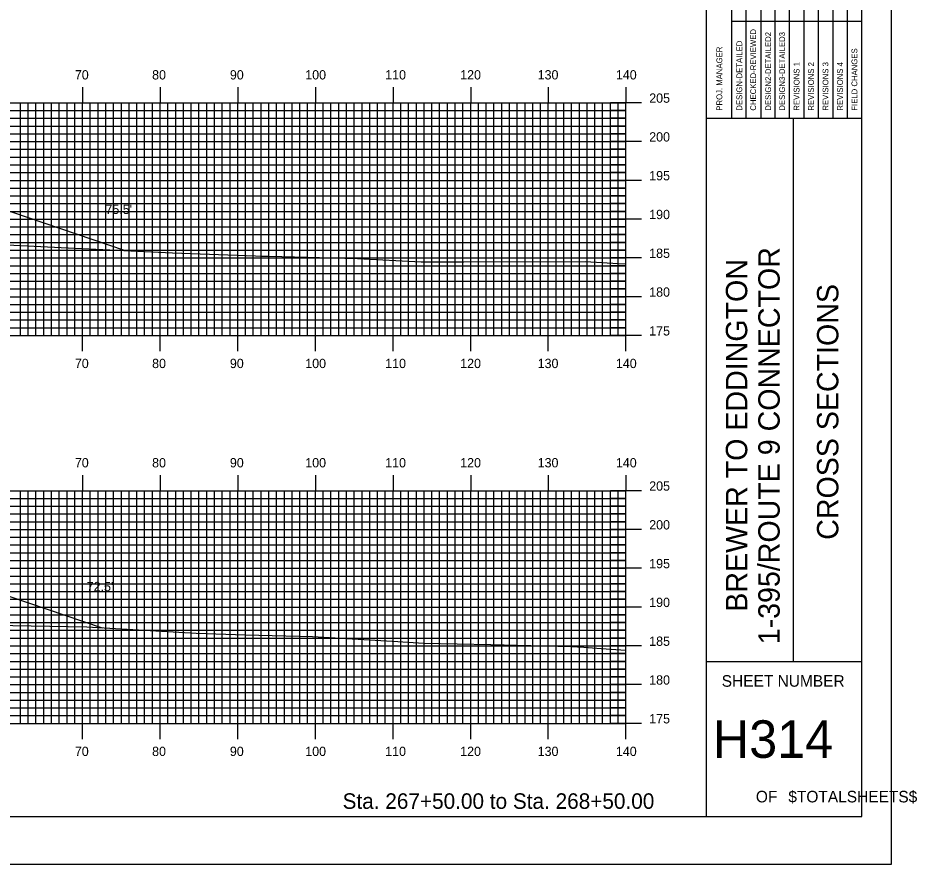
# Model space of a CAD drawing. Extents: x 1807832 to 1808175, y 442591 to 442811.
# Drawn here: x 1808059.5 to 1808175.3, y 442590.5 to 442699.6 of the extents above; entities that cross this region are included whole.
import ezdxf

# ---------------------------------------------------------------- set-up
doc = ezdxf.new("R2010")
doc.units = 0
for name, color, linetype in [('BORDER', 7, 'Continuous'), ('D_Roadway_SlopeLines', 7, 'Continuous'), ('D_Text_Standard', 7, 'Continuous'), ('H_V ANNOTATION', 7, 'Continuous'), ('MAJOR', 7, 'Continuous'), ('MINOR', 7, 'Continuous'), ('PLOT BOUNDARY', 7, 'Continuous'), ('S_Roadway_Centerline', 7, 'Continuous')]:
    doc.layers.add(name, color=color, linetype=linetype)

msp = doc.modelspace()

# ---------------------------------------------------------------- linework, layer by layer
at = {"layer": 'BORDER'}
for p, q in [((1808148.18, 442596.67), (1808148.18, 442806.67)), ((1808148.18, 442686.67), (1808168.18, 442686.67)), ((1808159.37, 442616.67), (1808159.37, 442686.67)), ((1808148.18, 442616.67), (1808168.18, 442616.67))]:
    msp.add_line(p, q, dxfattribs=at)
msp.add_lwpolyline([(1807848.18, 442596.67), (1808168.18, 442596.67), (1808168.18, 442806.67), (1807848.18, 442806.67)], close=True, dxfattribs=at)
for points in [[(1808153.28, 442686.68), (1808153.28, 442721.67)], [(1808155.14, 442721.67), (1808155.14, 442686.68)], [(1808157.01, 442686.68), (1808157.01, 442721.67)], [(1808158.87, 442686.68), (1808158.87, 442721.67)], [(1808160.73, 442686.68), (1808160.73, 442721.67)], [(1808162.6, 442686.68), (1808162.6, 442721.67)], [(1808164.46, 442686.68), (1808164.46, 442721.67)], [(1808166.32, 442686.68), (1808166.32, 442721.67)], [(1808151.42, 442686.68), (1808151.42, 442720.26)], [(1808151.41, 442699.17), (1808168.18, 442699.17)]]:
    msp.add_lwpolyline(points, dxfattribs=at)
at = {"layer": 'D_Roadway_SlopeLines'}
for points in [[(1808051.29, 442677.07), (1808054.53, 442675.97), (1808073.28, 442669.62)], [(1808043.37, 442630.1), (1808046.6, 442629.01), (1808070.29, 442620.99)]]:
    msp.add_lwpolyline(points, dxfattribs=at)
at = {"layer": 'MAJOR'}
for p, q in [((1808067.78, 442690.67), (1808067.78, 442688.67)), ((1808077.78, 442690.67), (1808077.78, 442688.67)), ((1808087.78, 442690.67), (1808087.78, 442688.67)), ((1808097.78, 442690.67), (1808097.78, 442688.67)), ((1808107.78, 442690.67), (1808107.78, 442688.67)), ((1808117.78, 442690.67), (1808117.78, 442688.67)), ((1808127.78, 442690.67), (1808127.78, 442688.67)), ((1808137.78, 442690.67), (1808137.78, 442688.67)), ((1807857.78, 442688.67), (1808137.78, 442688.67)), ((1807857.78, 442688.67), (1808137.78, 442688.67)), ((1808067.78, 442658.67), (1808067.78, 442688.67)), ((1808077.78, 442658.67), (1808077.78, 442688.67)), ((1808087.78, 442658.67), (1808087.78, 442688.67)), ((1808097.78, 442658.67), (1808097.78, 442688.67)), ((1808107.78, 442658.67), (1808107.78, 442688.67)), ((1808117.78, 442658.67), (1808117.78, 442688.67)), ((1808127.78, 442658.67), (1808127.78, 442688.67)), ((1808139.79, 442688.67), (1808135.78, 442688.67)), ((1808137.78, 442658.67), (1808137.78, 442688.67)), ((1808137.78, 442658.67), (1808137.78, 442688.67)), ((1807857.78, 442683.67), (1808137.78, 442683.67)), ((1808139.79, 442683.67), (1808135.78, 442683.67)), ((1807857.78, 442678.67), (1808137.78, 442678.67)), ((1808139.79, 442678.67), (1808135.78, 442678.67)), ((1807857.78, 442673.67), (1808137.78, 442673.67)), ((1808139.79, 442673.67), (1808135.78, 442673.67)), ((1807857.78, 442668.67), (1808137.78, 442668.67)), ((1808139.79, 442668.67), (1808135.78, 442668.67)), ((1807857.78, 442663.67), (1808137.78, 442663.67)), ((1808139.79, 442663.67), (1808135.78, 442663.67)), ((1807857.78, 442658.67), (1808137.78, 442658.67)), ((1807857.78, 442658.67), (1808137.78, 442658.67)), ((1808067.78, 442656.66), (1808067.78, 442658.67)), ((1808077.78, 442656.66), (1808077.78, 442658.67)), ((1808087.78, 442656.66), (1808087.78, 442658.67)), ((1808097.78, 442656.66), (1808097.78, 442658.67)), ((1808107.78, 442656.66), (1808107.78, 442658.67)), ((1808117.78, 442656.66), (1808117.78, 442658.67)), ((1808127.78, 442656.66), (1808127.78, 442658.67)), ((1808139.79, 442658.67), (1808135.78, 442658.67)), ((1808137.78, 442656.66), (1808137.78, 442658.67)), ((1808067.78, 442640.67), (1808067.78, 442638.67)), ((1808077.78, 442640.67), (1808077.78, 442638.67)), ((1808087.78, 442640.67), (1808087.78, 442638.67)), ((1808097.78, 442640.67), (1808097.78, 442638.67)), ((1808107.78, 442640.67), (1808107.78, 442638.67)), ((1808117.78, 442640.67), (1808117.78, 442638.67)), ((1808127.78, 442640.67), (1808127.78, 442638.67)), ((1808137.78, 442640.67), (1808137.78, 442638.67)), ((1807857.78, 442638.67), (1808137.78, 442638.67)), ((1807857.78, 442638.67), (1808137.78, 442638.67)), ((1808067.78, 442608.67), (1808067.78, 442638.67)), ((1808077.78, 442608.67), (1808077.78, 442638.67)), ((1808087.78, 442608.67), (1808087.78, 442638.67)), ((1808097.78, 442608.67), (1808097.78, 442638.67)), ((1808107.78, 442608.67), (1808107.78, 442638.67)), ((1808117.78, 442608.67), (1808117.78, 442638.67)), ((1808127.78, 442608.67), (1808127.78, 442638.67)), ((1808139.79, 442638.67), (1808135.78, 442638.67)), ((1808137.78, 442608.67), (1808137.78, 442638.67)), ((1808137.78, 442608.67), (1808137.78, 442638.67)), ((1807857.78, 442633.67), (1808137.78, 442633.67)), ((1808139.79, 442633.67), (1808135.78, 442633.67)), ((1807857.78, 442628.67), (1808137.78, 442628.67)), ((1808139.79, 442628.67), (1808135.78, 442628.67)), ((1807857.78, 442623.67), (1808137.78, 442623.67)), ((1808139.79, 442623.67), (1808135.78, 442623.67)), ((1807857.78, 442618.67), (1808137.78, 442618.67)), ((1808139.79, 442618.67), (1808135.78, 442618.67)), ((1807857.78, 442613.67), (1808137.78, 442613.67)), ((1808139.79, 442613.67), (1808135.78, 442613.67)), ((1807857.78, 442608.67), (1808137.78, 442608.67)), ((1807857.78, 442608.67), (1808137.78, 442608.67)), ((1808067.78, 442606.66), (1808067.78, 442608.67)), ((1808077.78, 442606.66), (1808077.78, 442608.67)), ((1808087.78, 442606.66), (1808087.78, 442608.67)), ((1808097.78, 442606.66), (1808097.78, 442608.67)), ((1808107.78, 442606.66), (1808107.78, 442608.67)), ((1808117.78, 442606.66), (1808117.78, 442608.67)), ((1808127.78, 442606.66), (1808127.78, 442608.67)), ((1808139.79, 442608.67), (1808135.78, 442608.67)), ((1808137.78, 442606.66), (1808137.78, 442608.67))]:
    msp.add_line(p, q, dxfattribs=at)
at = {"layer": 'MINOR'}
for p, q in [((1808059.78, 442658.67), (1808059.78, 442688.67)), ((1808060.78, 442658.67), (1808060.78, 442688.67)), ((1808061.78, 442658.67), (1808061.78, 442688.67)), ((1808062.78, 442658.67), (1808062.78, 442688.67)), ((1808063.78, 442658.67), (1808063.78, 442688.67)), ((1808064.78, 442658.67), (1808064.78, 442688.67)), ((1808065.78, 442658.67), (1808065.78, 442688.67)), ((1808066.78, 442658.67), (1808066.78, 442688.67)), ((1808068.78, 442658.67), (1808068.78, 442688.67)), ((1808069.78, 442658.67), (1808069.78, 442688.67)), ((1808070.78, 442658.67), (1808070.78, 442688.67)), ((1808071.78, 442658.67), (1808071.78, 442688.67)), ((1808072.78, 442658.67), (1808072.78, 442688.67)), ((1808073.78, 442658.67), (1808073.78, 442688.67)), ((1808074.78, 442658.67), (1808074.78, 442688.67)), ((1808075.78, 442658.67), (1808075.78, 442688.67)), ((1808076.78, 442658.67), (1808076.78, 442688.67)), ((1808078.78, 442658.67), (1808078.78, 442688.67)), ((1808079.78, 442658.67), (1808079.78, 442688.67)), ((1808080.78, 442658.67), (1808080.78, 442688.67)), ((1808081.78, 442658.67), (1808081.78, 442688.67)), ((1808082.78, 442658.67), (1808082.78, 442688.67)), ((1808083.78, 442658.67), (1808083.78, 442688.67)), ((1808084.78, 442658.67), (1808084.78, 442688.67)), ((1808085.78, 442658.67), (1808085.78, 442688.67)), ((1808086.78, 442658.67), (1808086.78, 442688.67)), ((1808088.78, 442658.67), (1808088.78, 442688.67)), ((1808089.78, 442658.67), (1808089.78, 442688.67)), ((1808090.78, 442658.67), (1808090.78, 442688.67)), ((1808091.78, 442658.67), (1808091.78, 442688.67)), ((1808092.78, 442658.67), (1808092.78, 442688.67)), ((1808093.78, 442658.67), (1808093.78, 442688.67)), ((1808094.78, 442658.67), (1808094.78, 442688.67)), ((1808095.78, 442658.67), (1808095.78, 442688.67)), ((1808096.78, 442658.67), (1808096.78, 442688.67)), ((1808098.78, 442658.67), (1808098.78, 442688.67)), ((1808099.78, 442658.67), (1808099.78, 442688.67)), ((1808100.78, 442658.67), (1808100.78, 442688.67)), ((1808101.78, 442658.67), (1808101.78, 442688.67)), ((1808102.78, 442658.67), (1808102.78, 442688.67)), ((1808103.78, 442658.67), (1808103.78, 442688.67)), ((1808104.78, 442658.67), (1808104.78, 442688.67)), ((1808105.78, 442658.67), (1808105.78, 442688.67)), ((1808106.78, 442658.67), (1808106.78, 442688.67)), ((1808108.78, 442658.67), (1808108.78, 442688.67)), ((1808109.78, 442658.67), (1808109.78, 442688.67)), ((1808110.78, 442658.67), (1808110.78, 442688.67)), ((1808111.78, 442658.67), (1808111.78, 442688.67)), ((1808112.78, 442658.67), (1808112.78, 442688.67)), ((1808113.78, 442658.67), (1808113.78, 442688.67)), ((1808114.78, 442658.67), (1808114.78, 442688.67)), ((1808115.78, 442658.67), (1808115.78, 442688.67)), ((1808116.78, 442658.67), (1808116.78, 442688.67)), ((1808118.78, 442658.67), (1808118.78, 442688.67)), ((1808119.78, 442658.67), (1808119.78, 442688.67)), ((1808120.78, 442658.67), (1808120.78, 442688.67)), ((1808121.78, 442658.67), (1808121.78, 442688.67)), ((1808122.78, 442658.67), (1808122.78, 442688.67)), ((1808123.78, 442658.67), (1808123.78, 442688.67)), ((1808124.78, 442658.67), (1808124.78, 442688.67)), ((1808125.78, 442658.67), (1808125.78, 442688.67)), ((1808126.78, 442658.67), (1808126.78, 442688.67)), ((1808128.78, 442658.67), (1808128.78, 442688.67)), ((1808129.78, 442658.67), (1808129.78, 442688.67)), ((1808130.78, 442658.67), (1808130.78, 442688.67)), ((1808131.78, 442658.67), (1808131.78, 442688.67)), ((1808132.78, 442658.67), (1808132.78, 442688.67)), ((1808133.78, 442658.67), (1808133.78, 442688.67)), ((1808134.78, 442658.67), (1808134.78, 442688.67)), ((1808135.78, 442658.67), (1808135.78, 442688.67)), ((1808136.78, 442658.67), (1808136.78, 442688.67)), ((1807857.78, 442687.67), (1808137.78, 442687.67)), ((1808137.78, 442687.67), (1808135.78, 442687.67)), ((1807857.78, 442686.67), (1808137.78, 442686.67)), ((1808137.78, 442686.67), (1808135.78, 442686.67)), ((1807857.78, 442685.67), (1808137.78, 442685.67)), ((1808137.78, 442685.67), (1808135.78, 442685.67)), ((1807857.78, 442684.67), (1808137.78, 442684.67)), ((1808137.78, 442684.67), (1808135.78, 442684.67)), ((1807857.78, 442682.67), (1808137.78, 442682.67)), ((1808137.78, 442682.67), (1808135.78, 442682.67)), ((1807857.78, 442681.67), (1808137.78, 442681.67)), ((1808137.78, 442681.67), (1808135.78, 442681.67)), ((1807857.78, 442680.67), (1808137.78, 442680.67)), ((1808137.78, 442680.67), (1808135.78, 442680.67)), ((1807857.78, 442679.67), (1808137.78, 442679.67)), ((1808137.78, 442679.67), (1808135.78, 442679.67)), ((1807857.78, 442677.67), (1808137.78, 442677.67)), ((1808137.78, 442677.67), (1808135.78, 442677.67)), ((1807857.78, 442676.67), (1808137.78, 442676.67)), ((1808137.78, 442676.67), (1808135.78, 442676.67)), ((1807857.78, 442675.67), (1808137.78, 442675.67)), ((1807857.78, 442674.67), (1808137.78, 442674.67)), ((1808137.78, 442675.67), (1808135.78, 442675.67)), ((1808137.78, 442674.67), (1808135.78, 442674.67)), ((1807857.78, 442672.67), (1808137.78, 442672.67)), ((1808137.78, 442672.67), (1808135.78, 442672.67)), ((1807857.78, 442671.67), (1808137.78, 442671.67)), ((1808137.78, 442671.67), (1808135.78, 442671.67)), ((1807857.78, 442670.67), (1808137.78, 442670.67)), ((1808137.78, 442670.67), (1808135.78, 442670.67)), ((1807857.78, 442669.67), (1808137.78, 442669.67)), ((1808137.78, 442669.67), (1808135.78, 442669.67)), ((1807857.78, 442667.67), (1808137.78, 442667.67)), ((1808137.78, 442667.67), (1808135.78, 442667.67)), ((1807857.78, 442666.67), (1808137.78, 442666.67)), ((1808137.78, 442666.67), (1808135.78, 442666.67)), ((1807857.78, 442665.67), (1808137.78, 442665.67)), ((1808137.78, 442665.67), (1808135.78, 442665.67)), ((1807857.78, 442664.67), (1808137.78, 442664.67)), ((1808137.78, 442664.67), (1808135.78, 442664.67)), ((1807857.78, 442662.67), (1808137.78, 442662.67)), ((1808137.78, 442662.67), (1808135.78, 442662.67)), ((1807857.78, 442661.67), (1808137.78, 442661.67)), ((1807857.78, 442660.67), (1808137.78, 442660.67)), ((1808137.78, 442661.67), (1808135.78, 442661.67)), ((1808137.78, 442660.67), (1808135.78, 442660.67)), ((1807857.78, 442659.67), (1808137.78, 442659.67)), ((1808137.78, 442659.67), (1808135.78, 442659.67)), ((1808059.78, 442608.67), (1808059.78, 442638.67)), ((1808060.78, 442608.67), (1808060.78, 442638.67)), ((1808061.78, 442608.67), (1808061.78, 442638.67)), ((1808062.78, 442608.67), (1808062.78, 442638.67)), ((1808063.78, 442608.67), (1808063.78, 442638.67)), ((1808064.78, 442608.67), (1808064.78, 442638.67)), ((1808065.78, 442608.67), (1808065.78, 442638.67)), ((1808066.78, 442608.67), (1808066.78, 442638.67)), ((1808068.78, 442608.67), (1808068.78, 442638.67)), ((1808069.78, 442608.67), (1808069.78, 442638.67)), ((1808070.78, 442608.67), (1808070.78, 442638.67)), ((1808071.78, 442608.67), (1808071.78, 442638.67)), ((1808072.78, 442608.67), (1808072.78, 442638.67)), ((1808073.78, 442608.67), (1808073.78, 442638.67)), ((1808074.78, 442608.67), (1808074.78, 442638.67)), ((1808075.78, 442608.67), (1808075.78, 442638.67)), ((1808076.78, 442608.67), (1808076.78, 442638.67)), ((1808078.78, 442608.67), (1808078.78, 442638.67)), ((1808079.78, 442608.67), (1808079.78, 442638.67)), ((1808080.78, 442608.67), (1808080.78, 442638.67)), ((1808081.78, 442608.67), (1808081.78, 442638.67)), ((1808082.78, 442608.67), (1808082.78, 442638.67)), ((1808083.78, 442608.67), (1808083.78, 442638.67)), ((1808084.78, 442608.67), (1808084.78, 442638.67)), ((1808085.78, 442608.67), (1808085.78, 442638.67)), ((1808086.78, 442608.67), (1808086.78, 442638.67)), ((1808088.78, 442608.67), (1808088.78, 442638.67)), ((1808089.78, 442608.67), (1808089.78, 442638.67)), ((1808090.78, 442608.67), (1808090.78, 442638.67)), ((1808091.78, 442608.67), (1808091.78, 442638.67)), ((1808092.78, 442608.67), (1808092.78, 442638.67)), ((1808093.78, 442608.67), (1808093.78, 442638.67)), ((1808094.78, 442608.67), (1808094.78, 442638.67)), ((1808095.78, 442608.67), (1808095.78, 442638.67)), ((1808096.78, 442608.67), (1808096.78, 442638.67)), ((1808098.78, 442608.67), (1808098.78, 442638.67)), ((1808099.78, 442608.67), (1808099.78, 442638.67)), ((1808100.78, 442608.67), (1808100.78, 442638.67)), ((1808101.78, 442608.67), (1808101.78, 442638.67)), ((1808102.78, 442608.67), (1808102.78, 442638.67)), ((1808103.78, 442608.67), (1808103.78, 442638.67)), ((1808104.78, 442608.67), (1808104.78, 442638.67)), ((1808105.78, 442608.67), (1808105.78, 442638.67)), ((1808106.78, 442608.67), (1808106.78, 442638.67)), ((1808108.78, 442608.67), (1808108.78, 442638.67)), ((1808109.78, 442608.67), (1808109.78, 442638.67)), ((1808110.78, 442608.67), (1808110.78, 442638.67)), ((1808111.78, 442608.67), (1808111.78, 442638.67)), ((1808112.78, 442608.67), (1808112.78, 442638.67)), ((1808113.78, 442608.67), (1808113.78, 442638.67)), ((1808114.78, 442608.67), (1808114.78, 442638.67)), ((1808115.78, 442608.67), (1808115.78, 442638.67)), ((1808116.78, 442608.67), (1808116.78, 442638.67)), ((1808118.78, 442608.67), (1808118.78, 442638.67)), ((1808119.78, 442608.67), (1808119.78, 442638.67)), ((1808120.78, 442608.67), (1808120.78, 442638.67)), ((1808121.78, 442608.67), (1808121.78, 442638.67)), ((1808122.78, 442608.67), (1808122.78, 442638.67)), ((1808123.78, 442608.67), (1808123.78, 442638.67)), ((1808124.78, 442608.67), (1808124.78, 442638.67)), ((1808125.78, 442608.67), (1808125.78, 442638.67)), ((1808126.78, 442608.67), (1808126.78, 442638.67)), ((1808128.78, 442608.67), (1808128.78, 442638.67)), ((1808129.78, 442608.67), (1808129.78, 442638.67)), ((1808130.78, 442608.67), (1808130.78, 442638.67)), ((1808131.78, 442608.67), (1808131.78, 442638.67)), ((1808132.78, 442608.67), (1808132.78, 442638.67)), ((1808133.78, 442608.67), (1808133.78, 442638.67)), ((1808134.78, 442608.67), (1808134.78, 442638.67)), ((1808135.78, 442608.67), (1808135.78, 442638.67)), ((1808136.78, 442608.67), (1808136.78, 442638.67)), ((1807857.78, 442637.67), (1808137.78, 442637.67)), ((1808137.78, 442637.67), (1808135.78, 442637.67)), ((1807857.78, 442636.67), (1808137.78, 442636.67)), ((1808137.78, 442636.67), (1808135.78, 442636.67)), ((1807857.78, 442635.67), (1808137.78, 442635.67)), ((1808137.78, 442635.67), (1808135.78, 442635.67)), ((1807857.78, 442634.67), (1808137.78, 442634.67)), ((1808137.78, 442634.67), (1808135.78, 442634.67)), ((1807857.78, 442632.67), (1808137.78, 442632.67)), ((1808137.78, 442632.67), (1808135.78, 442632.67)), ((1807857.78, 442631.67), (1808137.78, 442631.67)), ((1807857.78, 442630.67), (1808137.78, 442630.67)), ((1808137.78, 442631.67), (1808135.78, 442631.67)), ((1808137.78, 442630.67), (1808135.78, 442630.67)), ((1807857.78, 442629.67), (1808137.78, 442629.67)), ((1808137.78, 442629.67), (1808135.78, 442629.67)), ((1807857.78, 442627.67), (1808137.78, 442627.67)), ((1808137.78, 442627.67), (1808135.78, 442627.67)), ((1807857.78, 442626.67), (1808137.78, 442626.67)), ((1808137.78, 442626.67), (1808135.78, 442626.67)), ((1807857.78, 442625.67), (1808137.78, 442625.67)), ((1808137.78, 442625.67), (1808135.78, 442625.67)), ((1807857.78, 442624.67), (1808137.78, 442624.67)), ((1808137.78, 442624.67), (1808135.78, 442624.67)), ((1807857.78, 442622.67), (1808137.78, 442622.67)), ((1808137.78, 442622.67), (1808135.78, 442622.67)), ((1807857.78, 442621.67), (1808137.78, 442621.67)), ((1808137.78, 442621.67), (1808135.78, 442621.67)), ((1807857.78, 442620.67), (1808137.78, 442620.67)), ((1808137.78, 442620.67), (1808135.78, 442620.67)), ((1807857.78, 442619.67), (1808137.78, 442619.67)), ((1808137.78, 442619.67), (1808135.78, 442619.67)), ((1807857.78, 442617.67), (1808137.78, 442617.67)), ((1807857.78, 442616.67), (1808137.78, 442616.67)), ((1808137.78, 442617.67), (1808135.78, 442617.67)), ((1808137.78, 442616.67), (1808135.78, 442616.67)), ((1807857.78, 442615.67), (1808137.78, 442615.67)), ((1808137.78, 442615.67), (1808135.78, 442615.67)), ((1807857.78, 442614.67), (1808137.78, 442614.67)), ((1808137.78, 442614.67), (1808135.78, 442614.67)), ((1807857.78, 442612.67), (1808137.78, 442612.67)), ((1808137.78, 442612.67), (1808135.78, 442612.67)), ((1807857.78, 442611.67), (1808137.78, 442611.67)), ((1808137.78, 442611.67), (1808135.78, 442611.67)), ((1807857.78, 442610.67), (1808137.78, 442610.67)), ((1808137.78, 442610.67), (1808135.78, 442610.67)), ((1807857.78, 442609.67), (1808137.78, 442609.67)), ((1808137.78, 442609.67), (1808135.78, 442609.67))]:
    msp.add_line(p, q, dxfattribs=at)
at = {"layer": 'PLOT BOUNDARY'}
msp.add_lwpolyline([(1807832, 442590.55), (1808172, 442590.55), (1808172, 442810.55), (1807832, 442810.55)], close=True, dxfattribs=at)
at = {"layer": 'S_Roadway_Centerline'}
for points in [[(1808055.42, 442670.49), (1808065.01, 442670.01), (1808079.38, 442669.33), (1808090.06, 442668.92), (1808090.83, 442668.91), (1808091.82, 442668.89), (1808103.19, 442668.59), (1808111.4, 442668.16), (1808116.88, 442668.15), (1808132.56, 442668.2), (1808136.77, 442667.97), (1808137.78, 442667.92)], [(1808056.36, 442621.34), (1808068.31, 442621.1), (1808082.41, 442620.32), (1808088.76, 442620.09), (1808097.39, 442619.88), (1808108.38, 442619.24), (1808111.69, 442619.03), (1808120.37, 442618.84), (1808130.71, 442618.58), (1808132.34, 442618.51), (1808134.58, 442618.31), (1808137.78, 442618.11)]]:
    msp.add_lwpolyline(points, dxfattribs=at)

# ---------------------------------------------------------------- texts
at = {"layer": 'BORDER'}
for s, height, p in [('CHECKED-REVIEWED', 0.7455, (1808154.55, 442687.65)), ('DESIGN2-DETAILED2', 0.7455, (1808156.48, 442687.65)), ('DESIGN3-DETAILED3', 0.7455, (1808158.27, 442687.65)), ('DESIGN-DETAILED', 0.7455, (1808152.76, 442687.65)), ('PROJ. MANAGER', 0.7455, (1808150.19, 442687.65)), ('FIELD CHANGES', 0.7455, (1808167.59, 442687.65)), ('REVISIONS 1', 0.7455, (1808160.14, 442687.65)), ('REVISIONS 2', 0.7455, (1808162, 442687.65)), ('REVISIONS 3', 0.7455, (1808163.86, 442687.65)), ('REVISIONS 4', 0.7455, (1808165.73, 442687.65)), ('1-395/ROUTE 9 CONNECTOR', 2.7557, (1808157.59, 442618.87)), ('BREWER TO EDDINGTON', 2.7557, (1808153.41, 442623.07)), ('CROSS SECTIONS', 2.7557, (1808165.15, 442632.34))]:
    msp.add_text(s, height=height, rotation=90, dxfattribs=at).set_placement(p)
for s, height, p in [('SHEET NUMBER', 1.4905, (1808150.12, 442613.4)), ('H314', 4.839, (1808148.99, 442604.23)), ('OF', 1.491, (1808154.52, 442598.49)), ('$TOTALSHEETS$', 1.4905, (1808158.7, 442598.49))]:
    msp.add_text(s, height=height, dxfattribs=at).set_placement(p)
at = {"layer": 'D_Text_Standard'}
for s, p in [("75.5'", (1808070.73, 442674.33)), ("72.5'", (1808068.31, 442625.71))]:
    msp.add_text(s, height=1.2, dxfattribs=at).set_placement(p)
at = {"layer": 'H_V ANNOTATION'}
for s, height, p in [('70', 1.2, (1808066.79, 442691.67)), ('80', 1.2, (1808076.74, 442691.67)), ('90', 1.2, (1808086.76, 442691.67)), ('100', 1.2, (1808096.47, 442691.67)), ('110', 1.2, (1808106.77, 442691.67)), ('120', 1.2, (1808116.43, 442691.67)), ('130', 1.2, (1808126.41, 442691.67)), ('140', 1.2, (1808136.49, 442691.67)), ('205', 1.2, (1808140.78, 442688.67)), ('200', 1.2, (1808140.78, 442683.67)), ('195', 1.2, (1808140.78, 442678.67)), ('190', 1.2, (1808140.78, 442673.67)), ('185', 1.2, (1808140.78, 442668.67)), ('180', 1.2, (1808140.78, 442663.67)), ('175', 1.2, (1808140.78, 442658.67)), ('70', 1.2, (1808066.79, 442654.47)), ('80', 1.2, (1808076.74, 442654.47)), ('90', 1.2, (1808086.76, 442654.47)), ('100', 1.2, (1808096.47, 442654.47)), ('110', 1.2, (1808106.77, 442654.47)), ('120', 1.2, (1808116.43, 442654.47)), ('130', 1.2, (1808126.41, 442654.47)), ('140', 1.2, (1808136.49, 442654.47)), ('70', 1.2, (1808066.79, 442641.67)), ('80', 1.2, (1808076.74, 442641.67)), ('90', 1.2, (1808086.76, 442641.67)), ('100', 1.2, (1808096.47, 442641.67)), ('110', 1.2, (1808106.77, 442641.67)), ('120', 1.2, (1808116.43, 442641.67)), ('130', 1.2, (1808126.41, 442641.67)), ('140', 1.2, (1808136.49, 442641.67)), ('205', 1.2, (1808140.78, 442638.67)), ('200', 1.2, (1808140.78, 442633.67)), ('195', 1.2, (1808140.78, 442628.67)), ('190', 1.2, (1808140.78, 442623.67)), ('185', 1.2, (1808140.78, 442618.67)), ('180', 1.2, (1808140.78, 442613.67)), ('175', 1.2, (1808140.78, 442608.67)), ('70', 1.2, (1808066.79, 442604.47)), ('80', 1.2, (1808076.74, 442604.47)), ('90', 1.2, (1808086.76, 442604.47)), ('100', 1.2, (1808096.47, 442604.47)), ('110', 1.2, (1808106.77, 442604.47)), ('120', 1.2, (1808116.43, 442604.47)), ('130', 1.2, (1808126.41, 442604.47)), ('140', 1.2, (1808136.49, 442604.47)), ('Sta. 267+50.00 to Sta. 268+50.00', 2.0004, (1808101.28, 442597.66))]:
    msp.add_text(s, height=height, dxfattribs=at).set_placement(p)

doc.saveas('drawing.dxf')
